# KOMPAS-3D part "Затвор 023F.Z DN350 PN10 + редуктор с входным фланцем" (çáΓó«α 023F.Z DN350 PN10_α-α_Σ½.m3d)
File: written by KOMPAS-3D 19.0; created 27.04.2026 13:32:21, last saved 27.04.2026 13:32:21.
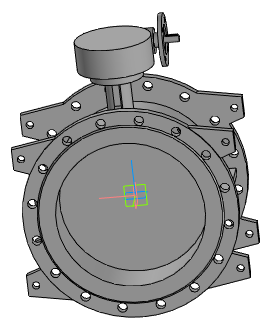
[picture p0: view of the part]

Document properties: Полное имя файла: ..\..\Затвор 023F.Z DN200-DN1600_редуктор с входным фланцем\Затвор 023F.Z DN350 PN10 + редуктор с входным фланцем.a3d

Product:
- Part/product: Затвор 023F.Z DN350 PN10 + редуктор с входным фланцем
    Масса: 129.379

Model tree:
1. Операция без истории:1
